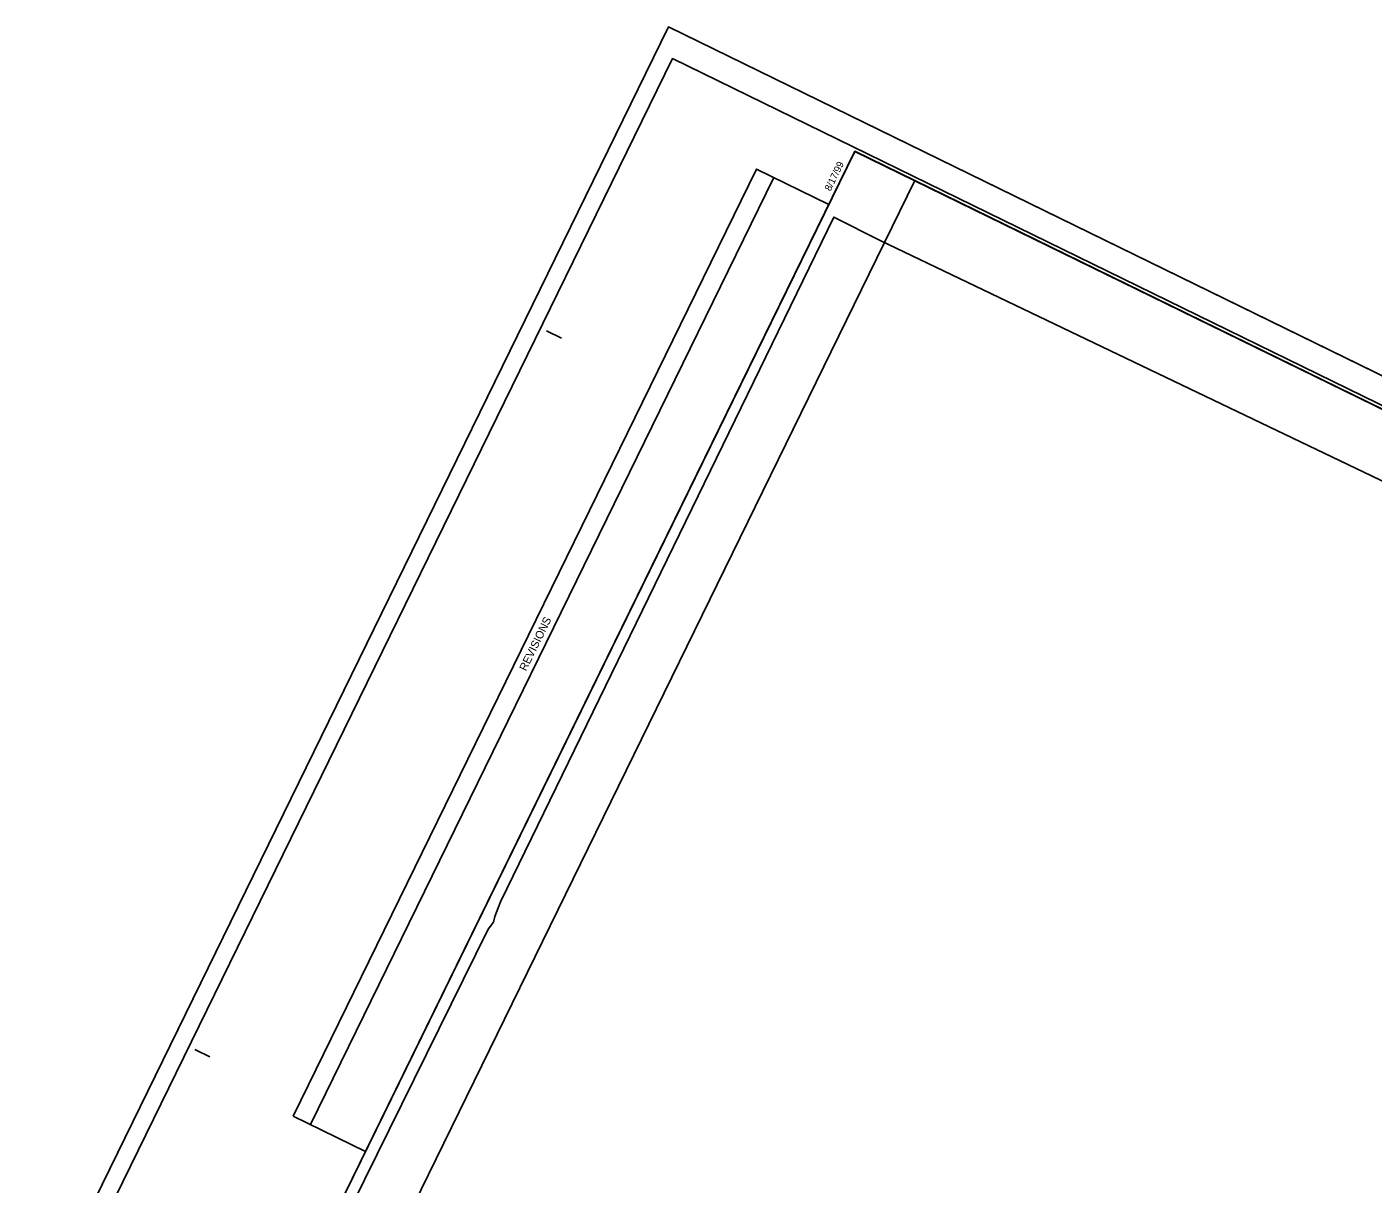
# Model space of a CAD drawing. Extents: x 1519210 to 1521378, y 637447 to 639183.
# Drawn here: x 1519210 to 1520219, y 638315 to 639183 of the extents above; entities that cross this region are included whole.
import ezdxf

# ---------------------------------------------------------------- set-up
doc = ezdxf.new("R2010")
doc.units = 0
for name, color, linetype in [('Sheet Block Revision CELL', 7, 'Continuous'), ('Sheet Clip Boundary CELL', 7, 'Continuous'), ('Sheet Cutting Line CELL', 7, 'Continuous'), ('Sheet Layout Plan Border', 7, 'Continuous'), ('Sheet Plan CELL', 7, 'Continuous'), ('Sheet Plan Layout CELL', 7, 'Continuous'), ('Sheet Plot Border Inside CELL', 7, 'Continuous'), ('Sheet Plot Border Outside CELL', 7, 'Continuous')]:
    doc.layers.add(name, color=color, linetype=linetype)

msp = doc.modelspace()

# ---------------------------------------------------------------- linework, layer by layer
at = {"layer": 'Sheet Block Revision CELL'}
msp.add_line((1519422.5, 638359.7), (1519769.9, 639069.9), dxfattribs=at)
msp.add_lwpolyline([(1519409.4, 638366), (1519756.8, 639076.3), (1519811.2, 639049.7), (1519463.8, 638339.5)], close=True, dxfattribs=at)
at = {"layer": 'Sheet Clip Boundary CELL'}
msp.add_lwpolyline([(1520331.1, 638792), (1519849.5, 639022.8), (1519814.9, 639040.3), (1519565, 638526.6), (1519563.2, 638522.3), (1519560.6, 638515.6), (1519559.8, 638511.5), (1519555.7, 638506.2), (1519379.7, 638149.4), (1519414.3, 638124.4), (1519623.4, 638028.4), (1519630, 638039.7), (1519661.2, 638093.4), (1519743.2, 638220.1), (1520032.2, 638075), (1519956.2, 637866.7), (1520671.9, 637509.3)], dxfattribs=at)
at = {"layer": 'Sheet Cutting Line CELL'}
for p, q in [((1519691, 639182.9), (1519209.9, 638199.2)), ((1521203.3, 638443.3), (1519691, 639182.9))]:
    msp.add_line(p, q, dxfattribs=at)
at = {"layer": 'Sheet Layout Plan Border'}
msp.add_lwpolyline([(1519414.3, 638124.4), (1520671.9, 637509.3), (1521040.3, 638262.5), (1520870.3, 638345.7), (1520963.2, 638535.7), (1519875.6, 639067.6)], close=True, dxfattribs=at)
at = {"layer": 'Sheet Plan CELL'}
for p, q in [((1519830.7, 639089.6), (1519830.7, 639089.6)), ((1519599.5, 638954.9), (1519610.7, 638949.4)), ((1519335.9, 638415.9), (1519347.1, 638410.4))]:
    msp.add_line(p, q, dxfattribs=at)
for points in [[(1521178.2, 638430.5), (1519830.7, 639089.6), (1519369.3, 638146.3), (1520716.8, 637487.3)], [(1519369.3, 638146.3), (1519830.6, 639089.5), (1520998.4, 638518.4), (1520906.3, 638330.1), (1521086, 638242.2), (1520716.8, 637487.3)]]:
    msp.add_lwpolyline(points, close=True, dxfattribs=at)
at = {"layer": 'Sheet Plan Layout CELL'}
msp.add_lwpolyline([(1519830.6, 639089.5), (1519369.3, 638146.3), (1520716.8, 637487.3), (1521085.2, 638240.6), (1520870.3, 638345.7), (1520963.2, 638535.7)], close=True, dxfattribs=at)
at = {"layer": 'Sheet Plot Border Inside CELL'}
msp.add_lwpolyline([(1519230.4, 638211.5), (1520727, 637479.6), (1521190.5, 638427.3), (1519693.9, 639159.2)], close=True, dxfattribs=at)
at = {"layer": 'Sheet Plot Border Outside CELL'}
msp.add_lwpolyline([(1519209.9, 638199.2), (1520722.2, 637459.6), (1521203.3, 638443.3), (1519691, 639182.9)], close=True, dxfattribs=at)

# ---------------------------------------------------------------- texts
at = {"layer": 'Sheet Block Revision CELL'}
msp.add_text('REVISIONS', height=6, rotation=63.9377, dxfattribs=at).set_placement((1519584.1, 638699.3))
at = {"layer": 'Sheet Plan CELL'}
msp.add_text('8/17/99', height=5.25, rotation=63.9377, dxfattribs=at).set_placement((1519812.3, 639059.3))

doc.saveas('drawing.dxf')
